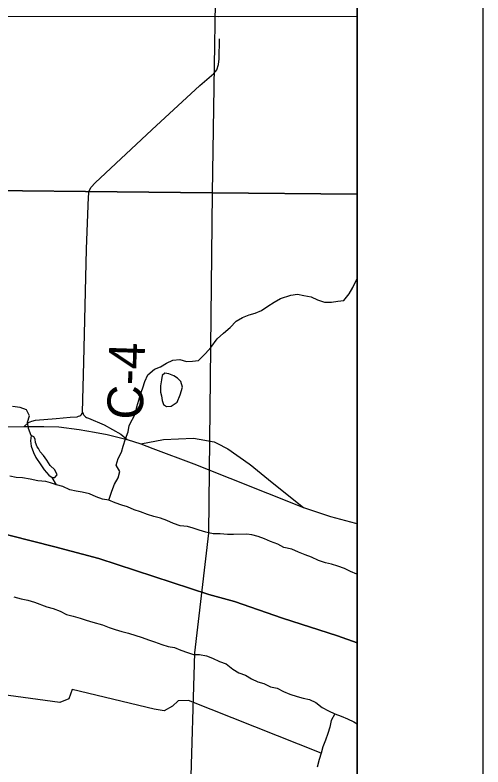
# Model space of a CAD drawing. Extents: x -6.2 to 37.4, y 0.2 to 22.2.
# Drawn here: x 8.209 to 8.581, y 19.007 to 19.604 of the extents above; entities that cross this region are included whole.
import ezdxf

# ---------------------------------------------------------------- set-up
doc = ezdxf.new("R2010")
doc.units = 0
for name, color, linetype in [('GM_X_County_Road', 7, 'Continuous'), ('GM_X_County_Road_Text', 7, 'Continuous'), ('GM_X_Major_River', 7, 'Continuous'), ('GM_X_Minor_Lake', 7, 'Continuous'), ('GM_X_Minor_River', 7, 'Continuous'), ('GM_X_Rail_Line', 7, 'Continuous'), ('GM_X_Section', 7, 'Continuous'), ('GM_X_Township_Road', 7, 'Continuous'), ('GM_X_US_Route', 7, 'Continuous'), ('GM_X_US_Shield', 7, 'Continuous'), ('SH_Data', 7, 'Continuous')]:
    doc.layers.add(name, color=color, linetype=linetype)

msp = doc.modelspace()

# ---------------------------------------------------------------- linework, layer by layer
at = {"layer": 'GM_X_County_Road'}
for points in [[(8.21636, 19.27727), (8.21976, 19.28034), (8.22239, 19.28143), (8.22535, 19.2822), (8.2418, 19.28363), (8.25276, 19.2845), (8.25832, 19.28495), (8.25962, 19.28529), (8.26042, 19.28564), (8.26135, 19.28623), (8.262, 19.28681), (8.26247, 19.28744), (8.26267, 19.28789), (8.26279, 19.28849), (8.26372, 19.32835), (8.2659, 19.41813), (8.26732, 19.4596), (8.26796, 19.46454), (8.26959, 19.46748), (8.27274, 19.47074), (8.31774, 19.51291), (8.35595, 19.54807), (8.367, 19.55758), (8.36951, 19.56072), (8.37071, 19.56488), (8.37137, 19.56938), (8.37151, 19.58524)], [(8.17589, 19.2765), (8.21636, 19.27727), (8.23182, 19.27727), (8.24388, 19.27694), (8.25989, 19.27485), (8.27228, 19.27277), (8.28237, 19.2708), (8.29817, 19.26685), (8.30902, 19.26334), (8.31845, 19.25983), (8.35102, 19.24744), (8.43832, 19.21278), (8.4597, 19.20566), (8.47961, 19.20034), (8.48086, 19.2001)]]:
    msp.add_lwpolyline(points, dxfattribs=at)
at = {"layer": 'GM_X_Major_River'}
for points in [[(8.23353, 19.23351), (8.22719, 19.23403), (8.22096, 19.23526), (8.2151, 19.23649), (8.20998, 19.23657), (8.20483, 19.23764)], [(8.48086, 19.15968), (8.48053, 19.15981), (8.47564, 19.16197), (8.47075, 19.16432), (8.46567, 19.16629), (8.46058, 19.16789), (8.45566, 19.16891), (8.4502, 19.1707), (8.44456, 19.17344), (8.43966, 19.17522), (8.4342, 19.17739), (8.42893, 19.17975), (8.42269, 19.18098), (8.41781, 19.18371), (8.41216, 19.18569), (8.40727, 19.18804), (8.40237, 19.18982), (8.39709, 19.19123), (8.39313, 19.1917), (8.38268, 19.19145), (8.37775, 19.19133), (8.37207, 19.19199), (8.36638, 19.19188), (8.36072, 19.1933), (8.35544, 19.19489), (8.35054, 19.19629), (8.34602, 19.19775), (8.34033, 19.19816), (8.33487, 19.20014), (8.3296, 19.20249), (8.3247, 19.20427), (8.31928, 19.20556), (8.31432, 19.20728), (8.30886, 19.20926), (8.30377, 19.21104), (8.29855, 19.21325), (8.29397, 19.21461), (8.28851, 19.21659), (8.28361, 19.21856), (8.27851, 19.21958), (8.27361, 19.22118), (8.26816, 19.22372), (8.26249, 19.22495), (8.25758, 19.22578), (8.25267, 19.227), (8.24702, 19.22955), (8.24212, 19.23095), (8.23722, 19.23254), (8.23353, 19.23351)], [(8.20818, 19.14174), (8.21384, 19.14032), (8.21913, 19.13911), (8.2246, 19.1375), (8.2344, 19.13394), (8.23949, 19.13254), (8.24496, 19.13037), (8.25003, 19.12782), (8.25531, 19.12641), (8.26079, 19.125), (8.26569, 19.12341), (8.27078, 19.12163), (8.27852, 19.11961), (8.28379, 19.11745), (8.28869, 19.11585), (8.29397, 19.11425), (8.29926, 19.11285), (8.3102, 19.10965), (8.31509, 19.10768), (8.31999, 19.10608), (8.32583, 19.10391), (8.33074, 19.10251), (8.33565, 19.10149), (8.34074, 19.09951), (8.34601, 19.09754), (8.35092, 19.09613), (8.35565, 19.09606)], [(8.35565, 19.09606), (8.36113, 19.09503), (8.36603, 19.09306), (8.37148, 19.09051), (8.37695, 19.08853), (8.382, 19.08447), (8.38688, 19.08156), (8.39215, 19.07958), (8.39703, 19.07666), (8.40192, 19.07431), (8.40682, 19.07291), (8.41209, 19.07037), (8.41738, 19.06915), (8.42245, 19.06661), (8.42753, 19.06444), (8.43319, 19.06265), (8.4381, 19.06125), (8.44301, 19.06023), (8.44809, 19.05788), (8.45314, 19.05401), (8.45821, 19.05128), (8.46329, 19.04893), (8.46818, 19.04696), (8.47327, 19.04479), (8.47816, 19.04245), (8.48086, 19.04093)]]:
    msp.add_lwpolyline(points, dxfattribs=at)
at = {"layer": 'GM_X_Minor_Lake'}
for p, q in [((8.32476, 19.30963), (8.3247, 19.30461)), ((8.22763, 19.25982), (8.22652, 19.26116))]:
    msp.add_line(p, q, dxfattribs=at)
for points in [[(8.3247, 19.30461), (8.32541, 19.30157), (8.3261, 19.29795), (8.327, 19.29471), (8.32943, 19.29297), (8.33304, 19.29348), (8.33783, 19.29645), (8.3404, 19.30248), (8.34202, 19.30833), (8.34077, 19.31309), (8.33816, 19.3156), (8.33535, 19.31735), (8.33139, 19.31911), (8.32799, 19.31954), (8.32598, 19.3177), (8.32541, 19.31423), (8.32476, 19.30963)], [(8.22652, 19.26116), (8.22525, 19.2646), (8.2251, 19.26706), (8.224, 19.26898), (8.22193, 19.26996), (8.22129, 19.2658), (8.22179, 19.26161), (8.22378, 19.25646), (8.22561, 19.25245), (8.22968, 19.2467), (8.23227, 19.24267), (8.23599, 19.23863), (8.23861, 19.2367), (8.2407, 19.23666), (8.24244, 19.23891), (8.24061, 19.24274), (8.23707, 19.2462), (8.2343, 19.25042), (8.23171, 19.25406), (8.22891, 19.25714), (8.22763, 19.25982)]]:
    msp.add_lwpolyline(points, dxfattribs=at)
at = {"layer": 'GM_X_Minor_River'}
for points in [[(8.28361, 19.21856), (8.28601, 19.22592), (8.28819, 19.23139), (8.29112, 19.23646), (8.29235, 19.24157), (8.2894, 19.24654), (8.29101, 19.25183), (8.29355, 19.25672), (8.29496, 19.26163), (8.29677, 19.26729), (8.29895, 19.27295), (8.29979, 19.27787), (8.30489, 19.28766), (8.30592, 19.29295), (8.30753, 19.29805), (8.30875, 19.30296), (8.31073, 19.30805), (8.31233, 19.31296), (8.3147, 19.31823), (8.31989, 19.32289), (8.32466, 19.32453), (8.32945, 19.32749), (8.33442, 19.32988), (8.34012, 19.33055), (8.34521, 19.32876), (8.35014, 19.32907), (8.35489, 19.32975), (8.36029, 19.33517), (8.36455, 19.34004), (8.36979, 19.34697), (8.3746, 19.35126), (8.37999, 19.35592), (8.38481, 19.36097), (8.38979, 19.36373), (8.39513, 19.36593), (8.39989, 19.36718), (8.40486, 19.36938), (8.41004, 19.37272), (8.41502, 19.37605), (8.42, 19.37901), (8.4282, 19.38154), (8.43352, 19.38241), (8.43862, 19.38119), (8.44429, 19.38016), (8.44937, 19.3778), (8.45502, 19.37601), (8.46052, 19.37592), (8.46546, 19.3768), (8.47021, 19.37729), (8.47466, 19.38272), (8.4774, 19.38761), (8.47995, 19.39269), (8.48086, 19.39462)], [(8.22193, 19.26996), (8.21975, 19.27568), (8.21889, 19.28063), (8.22049, 19.28573), (8.2183, 19.2905), (8.21321, 19.29229), (8.20716, 19.29314)], [(8.24212, 19.23095), (8.23861, 19.2367)], [(8.45233, 19.0176), (8.34688, 19.05939), (8.33872, 19.05913), (8.3341, 19.05484), (8.32759, 19.05114), (8.31965, 19.05259), (8.25451, 19.06818), (8.25173, 19.06083), (8.24467, 19.0579), (8.09468, 19.07821), (8.08801, 19.07641), (7.99184, 19.08416), (7.9849, 19.07782), (7.98256, 19.07368), (7.97168, 19.06911), (7.96536, 19.0656), (7.96196, 19.06622), (7.95132, 19.06487), (7.94394, 19.06555), (7.93938, 19.06543), (7.93485, 19.06607), (7.93221, 19.06687)], [(8.46329, 19.04893), (8.46036, 19.04366), (8.45912, 19.03818), (8.45752, 19.03327), (8.45573, 19.02798), (8.45355, 19.0227), (8.45233, 19.0176), (8.45073, 19.0125), (8.44911, 19.00646)]]:
    msp.add_lwpolyline(points, dxfattribs=at)
at = {"layer": 'GM_X_Rail_Line'}
for points in [[(7.57575, 19.08308), (7.64169, 19.15077), (7.6659, 19.17151), (7.68931, 19.1876), (7.70939, 19.19867), (7.72762, 19.20672), (7.78413, 19.22918), (7.81059, 19.23698), (7.83264, 19.24037), (7.89684, 19.24204), (7.92663, 19.24267), (7.95771, 19.24137), (8.00593, 19.2361), (8.04289, 19.23073), (8.08787, 19.22179), (8.13511, 19.20839), (8.24079, 19.1817), (8.27563, 19.17225), (8.36306, 19.14379), (8.38339, 19.13813), (8.42155, 19.12494), (8.46516, 19.11096), (8.48086, 19.10542), (8.48086, 21.10742)], [(8.48086, 17.70742), (8.48086, 19.10542), (8.46516, 19.11096), (8.42155, 19.12494), (8.38339, 19.13813), (8.36306, 19.14379), (8.27563, 19.17225), (8.24079, 19.1817), (8.13511, 19.20839), (8.08787, 19.22179), (8.04289, 19.23073), (8.00593, 19.2361), (7.95771, 19.24137), (7.92663, 19.24267), (7.89684, 19.24204), (7.83264, 19.24037), (7.81059, 19.23698), (7.78413, 19.22918), (7.72762, 19.20672), (7.70939, 19.19867), (7.68931, 19.1876), (7.6659, 19.17151), (7.64169, 19.15077), (7.57575, 19.08308)]]:
    msp.add_lwpolyline(points, dxfattribs=at)
at = {"layer": 'GM_X_Section'}
for points in [[(7.86961, 19.96985), (8.00052, 19.96891), (8.00317, 19.96906), (8.37373, 19.96735), (8.36573, 19.46292), (7.86279, 19.46826)], [(7.86279, 19.46826), (8.36573, 19.46292), (8.36276, 19.19242), (8.35159, 19.09748), (8.34824, 18.98196), (7.84124, 18.9938), (7.84473, 19.20159), (7.85975, 19.27675)]]:
    msp.add_lwpolyline(points, close=True, dxfattribs=at)
at = {"layer": 'GM_X_Township_Road'}
for points in [[(8.26279, 19.28849), (8.26325, 19.28725), (8.26383, 19.28619), (8.26438, 19.28555), (8.26516, 19.28492), (8.26591, 19.28445), (8.26736, 19.28371), (8.27985, 19.27847), (8.29301, 19.27102), (8.29817, 19.26685)], [(8.30902, 19.26334), (8.32692, 19.26692), (8.3508, 19.26781), (8.36725, 19.26498), (8.36935, 19.2639), (8.37817, 19.25937), (8.3951, 19.24762), (8.39728, 19.24582), (8.39871, 19.24464)], [(8.39871, 19.24464), (8.41331, 19.23263), (8.43832, 19.21278)]]:
    msp.add_lwpolyline(points, dxfattribs=at)
at = {"layer": 'GM_X_US_Route'}
msp.add_lwpolyline([(8.07715, 19.60318), (8.37094, 19.60307), (8.48086, 19.60317)], dxfattribs=at)
at = {"layer": 'GM_X_US_Shield'}
for points in [[(8.48086, 19.46188), (8.48086, 19.96755), (8.37373, 19.96735), (8.36573, 19.46292)], [(8.48086, 18.97901), (8.48086, 19.46188), (8.36573, 19.46292), (8.36276, 19.19242), (8.35159, 19.09748), (8.34824, 18.98196)]]:
    msp.add_lwpolyline(points, close=True, dxfattribs=at)
at = {"layer": 'SH_Data'}
for p, q in [((8.58086, 21.20742), (8.58086, 14.20742)), ((8.48086, 21.10742), (8.48086, 14.30742))]:
    msp.add_line(p, q, dxfattribs=at)

# ---------------------------------------------------------------- texts
at = {"layer": 'GM_X_County_Road_Text'}
msp.add_text('C-4', height=0.028409, rotation=88.16641, dxfattribs=at).set_placement((8.31047, 19.28232))

doc.saveas('drawing.dxf')
